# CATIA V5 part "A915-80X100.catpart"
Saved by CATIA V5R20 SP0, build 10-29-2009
Part number: A915-80X100
Source: Unknown
Property "A": "0.000"
Property "ARTICLENO": "A915-80X100"
Property "BOMINFO": "A915-80X100"
Property "CODE": "A915-80X100"
Property "CREATOR": "CADENAS GmbH"
Property "D": "13.500"
Property "D1": "20.000"
Property "FORM": "B"
Property "L": "100.000"
Property "L1": "25.000"
Property "L2": "50.000"
Property "LINA": "A915-80X100"
Property "NB": "A915-80X100"
Property "NBSYN": "$CODE."
Property "NN": "A915"
Property "NT": "VDI 3357 Wear Plates, steel"
Property "SCREW": "M12x25"
Property "SUPPLIER": "CF"
Property "T": "13.000"
Property "W": "80.000"
Bounding box of the stored display mesh (mm): x 0 to 20, y 0 to 100, z -40 to 40
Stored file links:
  C:\Users\borellobunino\Desktop\3D X SITO CF\A915\GSB_OILLESS_G22501080100\A915-80X100.catpart
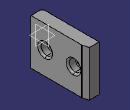
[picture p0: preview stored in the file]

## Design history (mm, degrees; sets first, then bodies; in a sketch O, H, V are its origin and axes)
Body1 "Geometry.1" (main body)
  Solid1 "A915-80X100.catpart": solid without history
